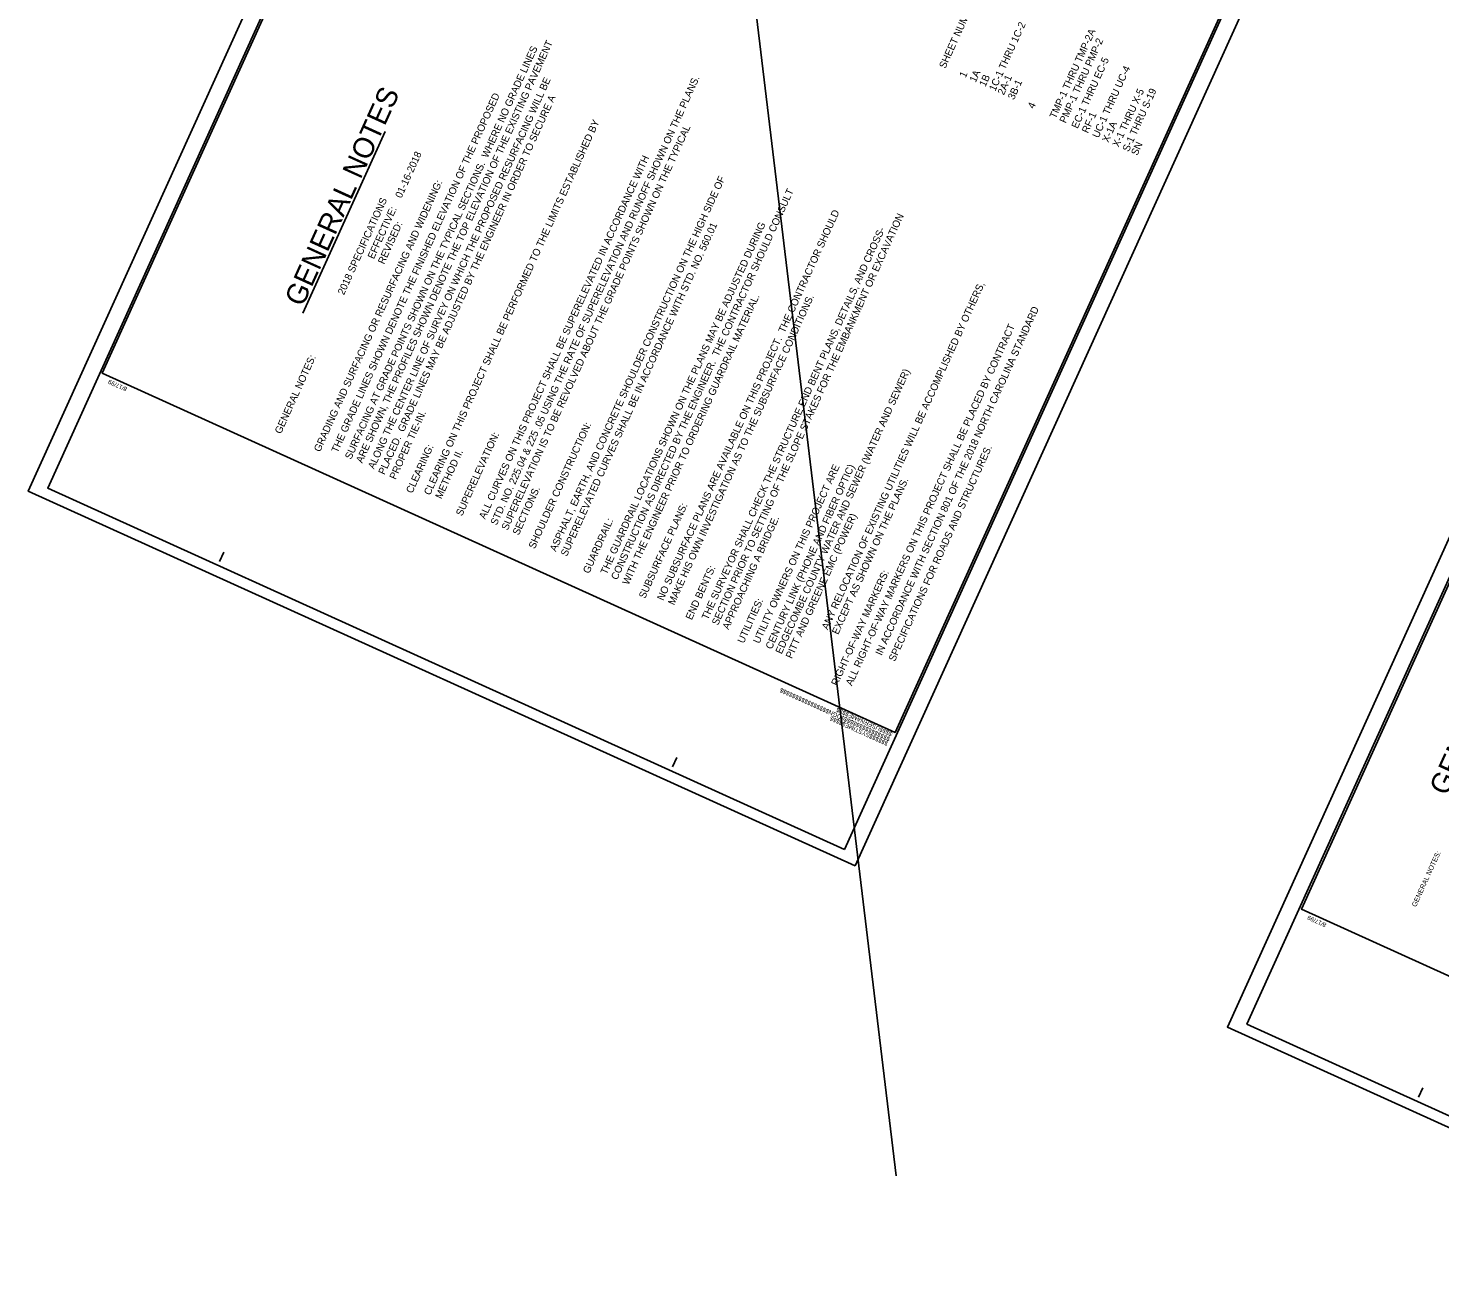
# Model space of a CAD drawing. Extents: x 1744741 to 2014229, y 466994 to 951338.
# Drawn here: x 2006218 to 2010049, y 473821 to 477236 of the extents above; entities that cross this region are included whole.
import ezdxf

# ---------------------------------------------------------------- set-up
doc = ezdxf.new("R2010")
doc.units = 0
for name, color, linetype in [('Default', 7, 'Continuous'), ('Old_Level_1', 7, 'Continuous'), ('Prop Guardrail Anchor Unit CELL', 7, 'Continuous'), ('Sheet Data Text CELL', 7, 'Continuous'), ('Sheet Plan CELL', 7, 'Continuous'), ('Sheet Plot Border Inside CELL', 7, 'Continuous'), ('Sheet Plot Border Outside CELL', 7, 'Continuous'), ('Sheet Sticker Preliminary CELL', 7, 'Continuous')]:
    doc.layers.add(name, color=color, linetype=linetype)

msp = doc.modelspace()

# ---------------------------------------------------------------- linework, layer by layer
at = {"layer": 'Old_Level_1'}
msp.add_line((2006963.4, 476463.1), (2007186.8, 476956.1), dxfattribs=at)
at = {"layer": 'Prop Guardrail Anchor Unit CELL'}
msp.add_line((2008573.3, 474121.5), (2007740.2, 481039.5), dxfattribs=at)
at = {"layer": 'Sheet Plan CELL'}
for p, q in [((2006736.8, 475789.1), (2006748.4, 475814.7)), ((2008570.5, 475324.8), (2008570.5, 475324.8)), ((2007966.3, 475231.8), (2007978, 475257.4)), ((2009991.2, 474334.9), (2010002.8, 474360.5))]:
    msp.add_line(p, q, dxfattribs=at)
for points in [[(2007812, 479374.1), (2006418.7, 476300.1), (2008570.5, 475324.8), (2009963.8, 478398.8)], [(2011066.5, 477919.9), (2009673.2, 474845.9), (2011825, 473870.6), (2013218.3, 476944.6)]]:
    msp.add_lwpolyline(points, close=True, dxfattribs=at)
at = {"layer": 'Sheet Plot Border Inside CELL'}
for points in [[(2008433, 475007.9), (2009980.5, 478422.1), (2007818.5, 479402), (2006271, 475987.9)], [(2011687.5, 473553.7), (2013235, 476967.9), (2011073, 477947.8), (2009525.5, 474533.7)]]:
    msp.add_lwpolyline(points, close=True, dxfattribs=at)
at = {"layer": 'Sheet Plot Border Outside CELL'}
for points in [[(2008462, 474962.7), (2010025.7, 478412.7), (2007781.7, 479429.8), (2006218, 475979.8)], [(2011716.4, 473508.5), (2013280.2, 476958.5), (2011036.2, 477975.6), (2009472.4, 474525.6)]]:
    msp.add_lwpolyline(points, close=True, dxfattribs=at)

# ---------------------------------------------------------------- texts
at = {"layer": 'Default'}
msp.add_text('GENERAL NOTES:                         2018 SPECIFICATIONS', height=13.5, rotation=65.6029, dxfattribs=at).set_placement((2009984.3, 474850.4))
at = {"layer": 'Old_Level_1'}
for s, height, p in [('GENERAL NOTES', 56.25, (2006962.8, 476477.9)), ('ANY RELOCATION OF EXISTING UTILITIES WILL BE ACCOMPLISHED BY OTHERS,', 19.688, (2008388, 475602)), ('EXCEPT AS SHOWN ON THE PLANS.', 19.688, (2008416.1, 475589.2)), ('GENERAL NOTES', 56.25, (2010069.5, 475150.7))]:
    msp.add_text(s, height=height, rotation=65.6171, dxfattribs=at).set_placement(p)
at = {"layer": 'Sheet Data Text CELL'}
for s, height, p in [('SHEET NUMBER                    SHEET   ', 19.688, (2008706.8, 477125.2)), ('1C-1 THRU 1C-2', 19.688, (2008842.3, 477063.8)), ('TMP-1 THRU TMP-2A', 19.688, (2009006.6, 476989.3)), ('PMP-1 THRU PMP-2', 19.688, (2009033.5, 476977.1)), ('EC-1 THRU EC-5', 19.688, (2009065.9, 476962.5)), ('UC-1 THRU UC-4', 19.688, (2009122.6, 476936.8)), ('1', 19.7, (2008761.8, 477100.3)), ('1A', 19.69, (2008789.3, 477087.8)), ('1B', 19.69, (2008815.6, 477075.9)), ('2A-1', 19.69, (2008865.6, 477053.3)), ('3B-1 ', 19.69, (2008893.3, 477040.7)), ('X-1 THRU X-5', 19.688, (2009177.1, 476912.1)), ('S-1 THRU S-19', 19.688, (2009204.6, 476899.6)), ('4 ', 19.69, (2008947.1, 477016.3)), ('RF-1', 19.69, (2009093.9, 476949.8)), ('X-1A', 19.69, (2009149.2, 476924.7)), ('SN', 19.69, (2009227.8, 476889.1))]:
    msp.add_text(s, height=height, rotation=65.6171, dxfattribs=at).set_placement(p)
at = {"layer": 'Sheet Plan CELL'}
for s, height, p in [('8/17/99', 11.81, (2006487.8, 476260.8)), ('$$$$$$$$$$$$$$$$DGN$$$$$$$$$$$$$$$$', 11.812, (2008558.6, 475311.3)), ('$$$$USERNAME$$$$', 11.812, (2008564.6, 475324.8)), ('$$$$$$SYSTIME$$$$$', 11.812, (2008552.9, 475298.9)), ('8/17/99', 11.81, (2009742.3, 474806.6))]:
    msp.add_text(s, height=height, rotation=155.6171, dxfattribs=at).set_placement(p)
at = {"layer": 'Sheet Sticker Preliminary CELL'}
for s, p in [('         SURFACING AT GRADE POINTS SHOWN ON THE TYPICAL SECTIONS.  WHERE NO GRADE LINES ', (2007067.1, 476004.6)), ('         ARE SHOWN, THE PROFILES SHOWN DENOTE THE TOP ELEVATION OF THE EXISTING PAVEMENT ', (2007097, 475994.6)), ('         ALONG THE CENTER LINE OF SURVEY ON WHICH THE PROPOSED RESURFACING WILL BE ', (2007129.3, 475978.2)), ('         STD. NO. 225.04 & 225 .05 USING THE RATE OF SUPERELEVATION AND RUNOFF SHOWN ON THE PLANS.', (2007462.1, 475825.9)), ('         THE GRADE LINES SHOWN DENOTE THE FINISHED ELEVATION OF THE PROPOSED ', (2007030.4, 476022.5)), ('         PLACED.  GRADE LINES MAY BE ADJUSTED BY THE ENGINEER IN ORDER TO SECURE A ', (2007157.6, 475963)), ('         CLEARING ON THIS PROJECT SHALL BE PERFORMED TO THE LIMITS ESTABLISHED BY ', (2007281.4, 475907.4)), ('         SUPERELEVATION IS TO BE REVOLVED ABOUT THE GRADE POINTS SHOWN ON THE TYPICAL ', (2007491.8, 475812.1)), ('                                       EFFECTIVE:    01-16-2018', (2007038.1, 476348.5)), ('         ALL CURVES ON THIS PROJECT SHALL BE SUPERELEVATED IN ACCORDANCE WITH', (2007430.8, 475842.2)), ('         ASPHALT, EARTH, AND CONCRETE SHOULDER CONSTRUCTION ON THE HIGH SIDE OF', (2007622.9, 475754.3)), ('GRADING AND SURFACING OR RESURFACING AND WIDENING:  ', (2007009.9, 476084.9)), ('         CONSTRUCTION AS DIRECTED BY THE ENGINEER.  THE CONTRACTOR SHOULD CONSULT', (2007789.2, 475677.6)), ('GENERAL NOTES:                         2018 SPECIFICATIONS', (2006903.8, 476133.8)), ('         NO SUBSURFACE PLANS ARE AVAILABLE ON THIS PROJECT.  THE CONTRACTOR SHOULD ', (2007914.2, 475621.5)), ('         SECTION PRIOR TO SETTING OF THE SLOPE STAKES FOR THE EMBANKMENT OR EXCAVATION ', (2008062.7, 475554.3)), ('                                       REVISED:      ', (2007066, 476334.4)), ('         SUPERELEVATED CURVES SHALL BE IN ACCORDANCE WITH STD. NO. 560.01', (2007652.6, 475741.4)), ('         THE GUARDRAIL LOCATIONS SHOWN ON THE PLANS MAY BE ADJUSTED DURING ', (2007760.7, 475692.2)), ('         THE SURVEYOR SHALL CHECK THE STRUCTURE END BENT PLANS, DETAILS, AND CROSS-', (2008035.2, 475569.1)), ('         WITH THE ENGINEER PRIOR TO ORDERING GUARDRAIL MATERIAL.', (2007820, 475664)), ('         MAKE HIS OWN INVESTIGATION AS TO THE SUBSURFACE CONDITIONS.  ', (2007943.6, 475609.2)), ('IN ACCORDANCE WITH SECTION 801 OF THE 2018 NORTH CAROLINA STANDARD', (2008534, 475532.4)), ('         ALL RIGHT-OF-WAY MARKERS ON THIS PROJECT SHALL BE PLACED BY CONTRACT ', (2008426, 475390.1)), ('         EDGECOMBE COUNTY WATER AND SEWER (WATER AND SEWER)', (2008235.4, 475476.4)), ('         PROPER TIE-IN.  ', (2007187.9, 475950)), ('SUPERELEVATION:  ', (2007395.4, 475910.9)), ('SHOULDER CONSTRUCTION:  ', (2007592.6, 475821.8)), ('CLEARING:  ', (2007260.2, 475972.3)), ('SPECIFICATIONS FOR ROADS AND STRUCTURES.', (2008569.9, 475516.2)), ('         METHOD II.', (2007312.2, 475897.4)), ('         UTILITY OWNERS ON THIS PROJECT ARE  ', (2008175, 475504.7)), ('         CENTURY LINK (PHONE AND FIBER OPTIC)', (2008208.5, 475489.1)), ('         SECTIONS.  ', (2007522.1, 475799)), ('SUBSURFACE PLANS:  ', (2007891.9, 475686.7)), ('         APPROACHING A BRIDGE.  ', (2008091.5, 475542.6)), ('         PITT AND GREENE EMC (POWER)', (2008263.2, 475463.9)), ('GUARDRAIL:  ', (2007740.2, 475754.7)), ('END BENTS:  ', (2008018.7, 475628.9)), ('RIGHT-OF-WAY MARKERS:  ', (2008413.9, 475450)), ('UTILITIES:  ', (2008159.7, 475565.2))]:
    msp.add_text(s, height=19.688, rotation=65.6171, dxfattribs=at).set_placement(p)

doc.saveas('drawing.dxf')
